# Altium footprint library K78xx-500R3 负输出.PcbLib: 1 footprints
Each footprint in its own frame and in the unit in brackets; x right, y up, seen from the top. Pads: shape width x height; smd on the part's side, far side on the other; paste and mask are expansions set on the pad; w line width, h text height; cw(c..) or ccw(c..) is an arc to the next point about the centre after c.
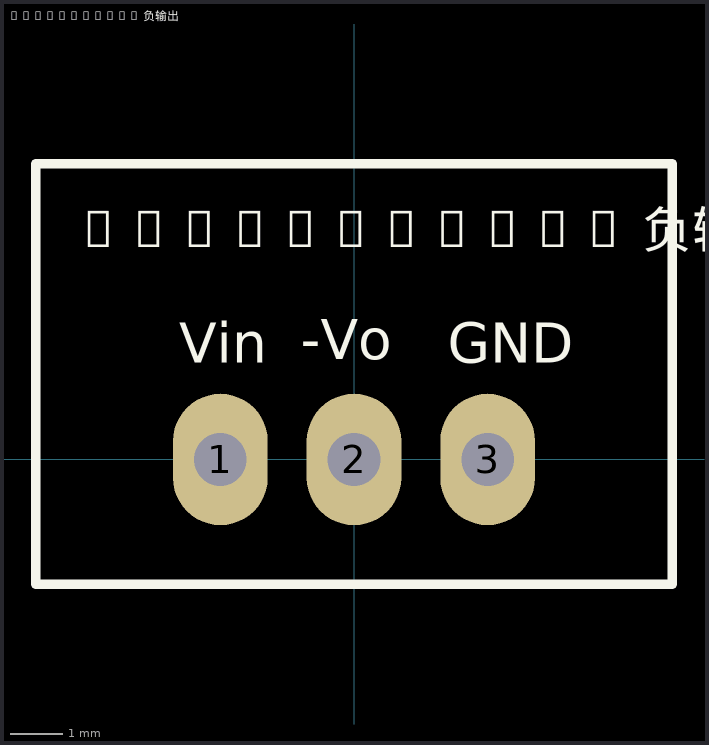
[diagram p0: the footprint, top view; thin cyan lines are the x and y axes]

## K78xx-500R3 负输出 [mm]
pads (3):
  oval 1.8x2.5 hole 1: 1(-2.54,0) 2(0,0) 3(2.54,0)
Top Overlay:
  lines w0.178: -6.05,-2.375 6.05,-2.375 6.05,5.625 -6.05,5.625 -6.05,-2.375
  text "GND" at 1.778,1.842 h0.76
  text "Vin" at -3.322,1.842 h0.76
  text "-Vo" at -1.016,1.905 h0.76
  text "K78xx-500R3 负输出" at -5.334,3.81 h1.2
Bottom Overlay:
  rectangle: 0.903,-2.088 1.646,1.477
  rectangle: -1.637,-2.088 -0.894,1.477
